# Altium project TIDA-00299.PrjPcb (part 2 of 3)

## Sheet AMIC110 ICE EVM_PHY.SchDoc
size 431 x 279 mm; Date: Not shown in title block; ApprovedBy: Not shown in title block; CheckedBy: Not shown in title block; Author: Not shown in title block; CompanyName: Not shown in title block; Engineer: Not shown in title block; Organization: Not shown in title block; Address1: Not shown in title block; Address2: Not shown in title block; Address3: Not shown in title block; Address4: Not shown in title block; DocumentNumber: 1; Revision: Use project parameter SCH_Rev; SheetNumber: 3; SheetTotal: 1; PageSetup: Record=PageOptions¦CenterHorizontal=True¦CenterVertical=True¦PrintScale=1.00¦XCorrection=1.00¦YCorrection=1.00¦PrintKind=0¦BorderSize=5000000¦LeftOffset=0¦BottomOffset=0¦Orientation=2¦PaperLength=1000¦PaperWidth=1000¦Scale=100¦PaperSource=15¦PrintQuality=600¦MediaType=1¦DitherType=10¦PaperKind=Letter¦PrintScaleMode=1
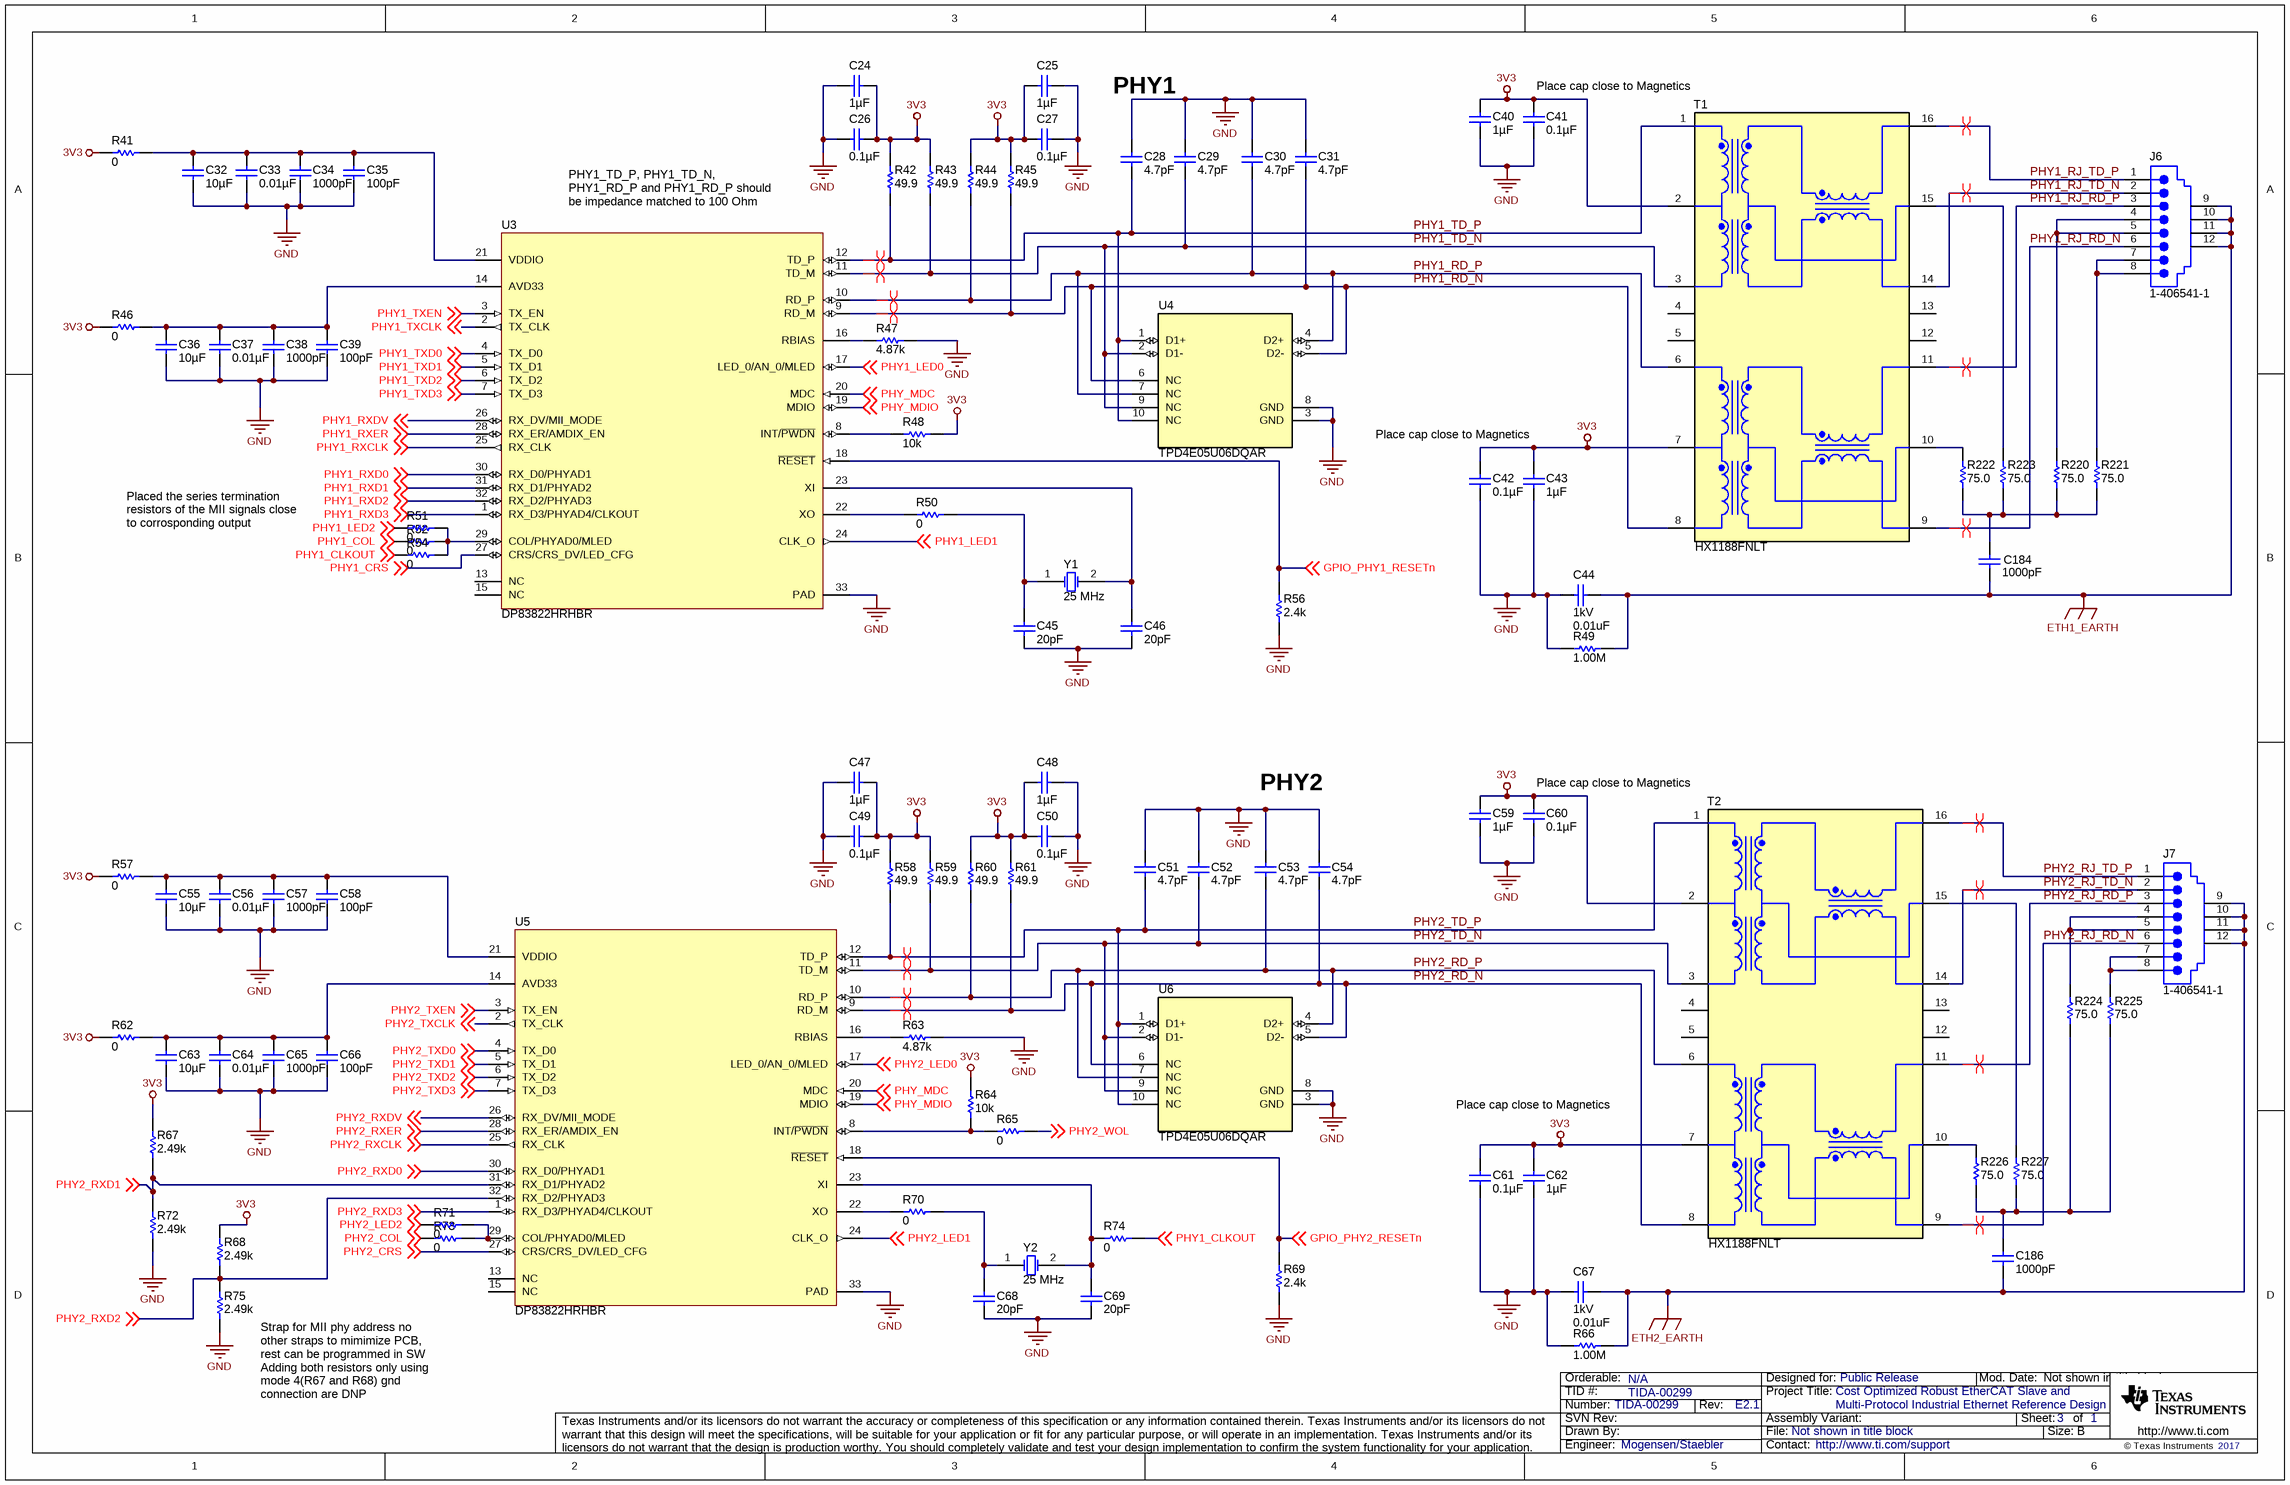
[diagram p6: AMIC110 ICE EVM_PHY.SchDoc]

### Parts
C24  ValueDisplayed: 1µF  [0402L]  (hidden comment: GRM155R70J105MA12D)
C25  ValueDisplayed: 1µF  [0402L]  (hidden comment: GRM155R70J105MA12D)
C26  ValueDisplayed: 0.1µF  [0402L]  (hidden comment: 885012205037)
C27  ValueDisplayed: 0.1µF  [0402L]  (hidden comment: 885012205037)
C28  ValueDisplayed: 4.7pF  [0201]  (hidden comment: GRM0335C1H4R7CA01D)
C29  ValueDisplayed: 4.7pF  [0201]  (hidden comment: GRM0335C1H4R7CA01D)
C30  ValueDisplayed: 4.7pF  [0201]  (hidden comment: GRM0335C1H4R7CA01D)
C31  ValueDisplayed: 4.7pF  [0201]  (hidden comment: GRM0335C1H4R7CA01D)
C32  ValueDisplayed: 10µF  [0805_HV]  (hidden comment: 885012207026)
C33  ValueDisplayed: 0.01µF  [0402]  (hidden comment: 885012205031)
C34  ValueDisplayed: 1000pF  [0402]  (hidden comment: 885012205044)
C35  ValueDisplayed: 100pF  [0402]  (hidden comment: CC0402KRX7R9BB101)
C36  ValueDisplayed: 10µF  [0805_HV]  (hidden comment: 885012207026)
C37  ValueDisplayed: 0.01µF  [0402]  (hidden comment: 885012205031)
C38  ValueDisplayed: 1000pF  [0402]  (hidden comment: 885012205044)
C39  ValueDisplayed: 100pF  [0402]  (hidden comment: CC0402KRX7R9BB101)
C40  ValueDisplayed: 1µF  [0402]  (hidden comment: GRM155R70J105MA12D)
C41  ValueDisplayed: 0.1µF  [0402]  (hidden comment: 885012205037)
C42  ValueDisplayed: 0.1µF  [0402]  (hidden comment: 885012205037)
C43  ValueDisplayed: 1µF  [0402]  (hidden comment: GRM155R70J105MA12D)
C44  VDC_V: 1kV  ValueDisplayed: 0.01uF  [1812_180]  (hidden comment: C1812C103KDRACTU)
C45  ValueDisplayed: 20pF  [0402]  (hidden comment: GRM1555C1H200JA01D)
C46  ValueDisplayed: 20pF  [0402]  (hidden comment: GRM1555C1H200JA01D)
C47  ValueDisplayed: 1µF  [0402L]  (hidden comment: GRM155R70J105MA12D)
C48  ValueDisplayed: 1µF  [0402L]  (hidden comment: GRM155R70J105MA12D)
C49  ValueDisplayed: 0.1µF  [0402L]  (hidden comment: 885012205037)
C50  ValueDisplayed: 0.1µF  [0402L]  (hidden comment: 885012205037)
C51  ValueDisplayed: 4.7pF  [0201]  (hidden comment: GRM0335C1H4R7CA01D)
C52  ValueDisplayed: 4.7pF  [0201]  (hidden comment: GRM0335C1H4R7CA01D)
C53  ValueDisplayed: 4.7pF  [0201]  (hidden comment: GRM0335C1H4R7CA01D)
C54  ValueDisplayed: 4.7pF  [0201]  (hidden comment: GRM0335C1H4R7CA01D)
C55  ValueDisplayed: 10µF  [0805_HV]  (hidden comment: 885012207026)
C56  ValueDisplayed: 0.01µF  [0402]  (hidden comment: 885012205031)
C57  ValueDisplayed: 1000pF  [0402]  (hidden comment: 885012205044)
C58  ValueDisplayed: 100pF  [0402]  (hidden comment: CC0402KRX7R9BB101)
C59  ValueDisplayed: 1µF  [0402]  (hidden comment: GRM155R70J105MA12D)
C60  ValueDisplayed: 0.1µF  [0402]  (hidden comment: 885012205037)
C61  ValueDisplayed: 0.1µF  [0402]  (hidden comment: 885012205037)
C62  ValueDisplayed: 1µF  [0402]  (hidden comment: GRM155R70J105MA12D)
C63  ValueDisplayed: 10µF  [0805_HV]  (hidden comment: 885012207026)
C64  ValueDisplayed: 0.01µF  [0402]  (hidden comment: 885012205031)
C65  ValueDisplayed: 1000pF  [0402]  (hidden comment: 885012205044)
C66  ValueDisplayed: 100pF  [0402]  (hidden comment: CC0402KRX7R9BB101)
C67  VDC_V: 1kV  ValueDisplayed: 0.01uF  [1812_180]  (hidden comment: C1812C103KDRACTU)
C68  ValueDisplayed: 20pF  [0402]  (hidden comment: GRM1555C1H200JA01D)
C69  ValueDisplayed: 20pF  [0402]  (hidden comment: GRM1555C1H200JA01D)
C184  ValueDisplayed: 1000pF  [1206_190]  (hidden comment: 202R18W102KV4E)
C186  ValueDisplayed: 1000pF  [1206_190]  (hidden comment: 202R18W102KV4E)
J6  1-406541-1  [TEC_1-406541-1]
J7  1-406541-1  [TEC_1-406541-1]
R41  ValueDisplayed: 0  [0402]  (hidden comment: CRCW04020000Z0ED)
R42  ValueDisplayed: 49.9  [0402L]  (hidden comment: CRCW040249R9FKED)
R43  ValueDisplayed: 49.9  [0402L]  (hidden comment: CRCW040249R9FKED)
R44  ValueDisplayed: 49.9  [0402L]  (hidden comment: CRCW040249R9FKED)
R45  ValueDisplayed: 49.9  [0402L]  (hidden comment: CRCW040249R9FKED)
R46  ValueDisplayed: 0  [0402]  (hidden comment: CRCW04020000Z0ED)
R47  ValueDisplayed: 4.87k  [0402]  (hidden comment: CRCW04024K87FKED)
R48  ValueDisplayed: 10k  [0402L]  (hidden comment: CRCW040210K0JNED)
R49  ValueDisplayed: 1.00M  [2010]  (hidden comment: HVC2010-1M0GT3)
R50  ValueDisplayed: 0  [0402]  (hidden comment: CRCW04020000Z0ED)
R51  ValueDisplayed: 0  [0402L]  (hidden comment: CRCW04020000Z0ED)
R52  ValueDisplayed: 0  [0402L]  (hidden comment: CRCW04020000Z0ED)
R54  ValueDisplayed: 0  [0402L]  (hidden comment: CRCW04020000Z0ED)
R56  ValueDisplayed: 2.4k  [0402]  (hidden comment: CRCW04022K40JNED)
R57  ValueDisplayed: 0  [0402]  (hidden comment: CRCW04020000Z0ED)
R58  ValueDisplayed: 49.9  [0402L]  (hidden comment: CRCW040249R9FKED)
R59  ValueDisplayed: 49.9  [0402L]  (hidden comment: CRCW040249R9FKED)
R60  ValueDisplayed: 49.9  [0402L]  (hidden comment: CRCW040249R9FKED)
R61  ValueDisplayed: 49.9  [0402L]  (hidden comment: CRCW040249R9FKED)
R62  ValueDisplayed: 0  [0402]  (hidden comment: CRCW04020000Z0ED)
R63  ValueDisplayed: 4.87k  [0402]  (hidden comment: CRCW04024K87FKED)
R64  ValueDisplayed: 10k  [0402]  (hidden comment: CRCW040210K0JNED)
R65  ValueDisplayed: 0  [0402]  (hidden comment: CRCW04020000Z0ED)
R66  ValueDisplayed: 1.00M  [2010]  (hidden comment: HVC2010-1M0GT3)
R67  ValueDisplayed: 2.49k  [0402L]  (hidden comment: CRCW04022K49FKED)
R68  ValueDisplayed: 2.49k  [0402L]  (hidden comment: CRCW04022K49FKED)
R69  ValueDisplayed: 2.4k  [0402]  (hidden comment: CRCW04022K40JNED)
R70  ValueDisplayed: 0  [0402]  (hidden comment: CRCW04020000Z0ED)
R71  ValueDisplayed: 0  [0402L]  (hidden comment: CRCW04020000Z0ED)
R72  ValueDisplayed: 2.49k  [0402L]  (hidden comment: CRCW04022K49FKED)
R73  ValueDisplayed: 0  [0402L]  (hidden comment: CRCW04020000Z0ED)
R74  ValueDisplayed: 0  [0402L]  (hidden comment: CRCW04020000Z0ED)
R75  ValueDisplayed: 2.49k  [0402L]  (hidden comment: CRCW04022K49FKED)
R220  ValueDisplayed: 75.0  [0805_HV]  (hidden comment: CRCW080575R0FKEA)
R221  ValueDisplayed: 75.0  [0805_HV]  (hidden comment: CRCW080575R0FKEA)
R222  ValueDisplayed: 75.0  [0805_HV]  (hidden comment: CRCW080575R0FKEA)
R223  ValueDisplayed: 75.0  [0805_HV]  (hidden comment: CRCW080575R0FKEA)
R224  ValueDisplayed: 75.0  [0805_HV]  (hidden comment: CRCW080575R0FKEA)
R225  ValueDisplayed: 75.0  [0805_HV]  (hidden comment: CRCW080575R0FKEA)
R226  ValueDisplayed: 75.0  [0805_HV]  (hidden comment: CRCW080575R0FKEA)
R227  ValueDisplayed: 75.0  [0805_HV]  (hidden comment: CRCW080575R0FKEA)
T1  HX1188FNLT  [Pulse_HX1188FNLT]
T2  HX1188FNLT  [Pulse_HX1188FNLT]
U3  DP83822HRHBR  [RHB0032B]
U4  TPD4E05U06DQAR  [DQA0010A]
U5  DP83822HRHBR  [RHB0032B]
U6  TPD4E05U06DQAR  [DQA0010A]
Y1  Frequency: 25 MHz  [XTAL_ABM3]  (hidden comment: CTX1175TR-ND)
Y2  Frequency: 25 MHz  [XTAL_ABM3]  (hidden comment: CTX1175TR-ND)

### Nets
3V3: C24.2 C25.1 C26.2 C27.1 C40.1 C41.1 C42.1 C43.1 C47.2 C48.1 C49.2 C50.1 C59.1 C60.1 C61.1 C62.1 R41.2 R42.2 R43.2 R44.2 R45.2 R46.2 R48.1 R57.2 R58.2 R59.2 R60.2 R61.2 R62.2 R64.2 R67.2 R68.2 T1.2(TCT) T1.7(RCT) T2.2(TCT) T2.7(RCT)
ETH1_EARTH: C44.1 C184.2 J6.9 J6.10 J6.11 J6.12 R49.2
ETH2_EARTH: C67.1 C186.2 J7.9 J7.10 J7.11 J7.12 R66.2
GND: C24.1 C25.2 C26.1 C27.2 C28.1 C29.1 C30.1 C31.1 C32.2 C33.2 C34.2 C35.2 C36.2 C37.2 C38.2 C39.2 C40.2 C41.2 C42.2 C43.2 C44.2 C45.2 C46.2 C47.1 C48.2 C49.1 C50.2 C51.1 C52.1 C53.1 C54.1 C55.2 C56.2 C57.2 C58.2 C59.2 C60.2 C61.2 C62.2 C63.2 C64.2 C65.2 C66.2 C67.2 C68.2 C69.1 R47.2 R49.1 R56.1 R63.2 R66.1 R69.1 R72.1 R75.1 U3.33(PAD) U4.3(GND) U4.8(GND) U5.33(PAD) U6.3(GND) U6.8(GND)
GPIO_PHY1_RESETn: R56.2 U3.18(~{RESET}) ; off-sheet GPIO_PHY1_RESETn
GPIO_PHY2_RESETn: R69.2 U5.18(~{RESET}) ; off-sheet GPIO_PHY2_RESETn
PHY1_CLKOUT: R54.1 R74.2 ; off-sheet PHY1_CLKOUT
PHY1_COL: R52.1 ; off-sheet PHY1_COL
PHY1_CRS: U3.27(CRS/CRS_DV/LED_CFG) ; off-sheet PHY1_CRS
PHY1_LED0: U3.17(LED_0/AN_0/MLED) ; off-sheet PHY1_LED0
PHY1_LED1: U3.24(CLK_O) ; off-sheet PHY1_LED1
PHY1_LED2: R51.1 ; off-sheet PHY1_LED2
PHY1_RD_N: C31.2 R45.1 T1.8(RD-) U3.9(RD_M) U4.5(D2-) U4.6(NC)
PHY1_RD_P: C30.2 R44.1 T1.6(RD+) U3.10(RD_P) U4.4(D2+) U4.7(NC)
PHY1_RJ_RD_N: J6.6 T1.9(RX-)
PHY1_RJ_RD_P: J6.3 T1.11(RX+)
PHY1_RJ_TD_N: J6.2 T1.14(TX-)
PHY1_RJ_TD_P: J6.1 T1.16(TX+)
PHY1_RXCLK: U3.25(RX_CLK) ; off-sheet PHY1_RXCLK
PHY1_RXD0: U3.30(RX_D0/PHYAD1) ; off-sheet PHY1_RXD0
PHY1_RXD1: U3.31(RX_D1/PHYAD2) ; off-sheet PHY1_RXD1
PHY1_RXD2: U3.32(RX_D2/PHYAD3) ; off-sheet PHY1_RXD2
PHY1_RXD3: U3.1(RX_D3/PHYAD4/CLKOUT) ; off-sheet PHY1_RXD3
PHY1_RXDV: U3.26(RX_DV/MII_MODE) ; off-sheet PHY1_RXDV
PHY1_RXER: U3.28(RX_ER/AMDIX_EN) ; off-sheet PHY1_RXER
PHY1_TD_N: C29.2 R43.1 T1.3(TD-) U3.11(TD_M) U4.2(D1-) U4.9(NC)
PHY1_TD_P: C28.2 R42.1 T1.1(TD+) U3.12(TD_P) U4.1(D1+) U4.10(NC)
PHY1_TXCLK: U3.2(TX_CLK) ; off-sheet PHY1_TXCLK
PHY1_TXD0: U3.4(TX_D0) ; off-sheet PHY1_TXD0
PHY1_TXD1: U3.5(TX_D1) ; off-sheet PHY1_TXD1
PHY1_TXD2: U3.6(TX_D2) ; off-sheet PHY1_TXD2
PHY1_TXD3: U3.7(TX_D3) ; off-sheet PHY1_TXD3
PHY1_TXEN: U3.3(TX_EN) ; off-sheet PHY1_TXEN
PHY2_COL: R73.1 ; off-sheet PHY2_COL
PHY2_CRS: U5.27(CRS/CRS_DV/LED_CFG) ; off-sheet PHY2_CRS
PHY2_LED0: U5.17(LED_0/AN_0/MLED) ; off-sheet PHY2_LED0
PHY2_LED1: U5.24(CLK_O) ; off-sheet PHY2_LED1
PHY2_LED2: R71.1 ; off-sheet PHY2_LED2
PHY2_RD_N: C54.2 R61.1 T2.8(RD-) U5.9(RD_M) U6.5(D2-) U6.6(NC)
PHY2_RD_P: C53.2 R60.1 T2.6(RD+) U5.10(RD_P) U6.4(D2+) U6.7(NC)
PHY2_RJ_RD_N: J7.6 T2.9(RX-)
PHY2_RJ_RD_P: J7.3 T2.11(RX+)
PHY2_RJ_TD_N: J7.2 T2.14(TX-)
PHY2_RJ_TD_P: J7.1 T2.16(TX+)
PHY2_RXCLK: U5.25(RX_CLK) ; off-sheet PHY2_RXCLK
PHY2_RXD0: U5.30(RX_D0/PHYAD1) ; off-sheet PHY2_RXD0
PHY2_RXD1: R67.1 R72.2 U5.31(RX_D1/PHYAD2) ; off-sheet PHY2_RXD1
PHY2_RXD2: R68.1 R75.2 U5.32(RX_D2/PHYAD3) ; off-sheet PHY2_RXD2
PHY2_RXD3: U5.1(RX_D3/PHYAD4/CLKOUT) ; off-sheet PHY2_RXD3
PHY2_RXDV: U5.26(RX_DV/MII_MODE) ; off-sheet PHY2_RXDV
PHY2_RXER: U5.28(RX_ER/AMDIX_EN) ; off-sheet PHY2_RXER
PHY2_TD_N: C52.2 R59.1 T2.3(TD-) U5.11(TD_M) U6.2(D1-) U6.9(NC)
PHY2_TD_P: C51.2 R58.1 T2.1(TD+) U5.12(TD_P) U6.1(D1+) U6.10(NC)
PHY2_TXCLK: U5.2(TX_CLK) ; off-sheet PHY2_TXCLK
PHY2_TXD0: U5.4(TX_D0) ; off-sheet PHY2_TXD0
PHY2_TXD1: U5.5(TX_D1) ; off-sheet PHY2_TXD1
PHY2_TXD2: U5.6(TX_D2) ; off-sheet PHY2_TXD2
PHY2_TXD3: U5.7(TX_D3) ; off-sheet PHY2_TXD3
PHY2_TXEN: U5.3(TX_EN) ; off-sheet PHY2_TXEN
PHY2_WOL: R65.2 ; off-sheet PHY2_WOL
PHY_MDC: U3.20(MDC) U5.20(MDC) ; off-sheet PHY_MDC
PHY_MDIO: U3.19(MDIO) U5.19(MDIO) ; off-sheet PHY_MDIO
NetC32_1: C32.1 C33.1 C34.1 C35.1 R41.1 U3.21(VDDIO)
NetC36_1: C36.1 C37.1 C38.1 C39.1 R46.1 U3.14(AVD33)
NetC45_1: C45.1 R50.2 Y1.1(OSC1)
NetC46_1: C46.1 U3.23(XI) Y1.2(OSC2)
NetC55_1: C55.1 C56.1 C57.1 C58.1 R57.1 U5.21(VDDIO)
NetC63_1: C63.1 C64.1 C65.1 C66.1 R62.1 U5.14(AVD33)
NetC68_1: C68.1 R70.2 Y2.1(OSC1)
NetC69_2: C69.2 R74.1 U5.23(XI) Y2.2(OSC2)
NetC184_1: C184.1 R220.1 R221.1 R222.1 R223.1
NetC186_1: C186.1 R224.1 R225.1 R226.1 R227.1
NetJ6_4: J6.4 J6.5 R220.2
NetJ6_7: J6.7 J6.8 R221.2
NetJ7_4: J7.4 J7.5 R224.2
NetJ7_7: J7.7 J7.8 R225.2
NetR47_1: R47.1 U3.16(RBIAS)
NetR48_2: R48.2 U3.8(INT/~{PWDN})
NetR50_1: R50.1 U3.22(XO)
NetR51_2: R51.2 R52.2 R54.2 U3.29(COL/PHYAD0/MLED)
NetR63_1: R63.1 U5.16(RBIAS)
NetR64_1: R64.1 R65.1 U5.8(INT/~{PWDN})
NetR70_1: R70.1 U5.22(XO)
NetR71_2: R71.2 R73.2 U5.29(COL/PHYAD0/MLED)
NetR222_2: R222.2 T1.10(CMT)
NetR223_2: R223.2 T1.15(CMT)
NetR226_2: R226.2 T2.10(CMT)
NetR227_2: R227.2 T2.15(CMT)

Not connected (* = marked no-connect by the designer): T1 4(NC) 5(NC) 12(NC) 13(NC); T2 4(NC) 5(NC) 12(NC) 13(NC); U3 13(NC) 15(NC); U5 13(NC) 15(NC)

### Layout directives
differential pair: PHY1_RD_N, PHY1_RD_P, PHY1_RJ_RD_N, PHY1_RJ_RD_P, PHY1_RJ_TD_N, PHY1_RJ_TD_P, PHY1_TD_N, PHY1_TD_P, PHY2_RD_N, PHY2_RD_P, PHY2_RJ_RD_N, PHY2_RJ_RD_P, PHY2_RJ_TD_N, PHY2_RJ_TD_P, PHY2_TD_N, PHY2_TD_P

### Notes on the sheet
- PHY1
- Place cap close to Magnetics
- PHY1_TD_P, PHY1_TD_N, PHY1_RD_P and PHY1_RD_P should be impedance matched to 100 Ohm
- Placed the series termination resistors of the MII signals close to corrosponding output
- PHY2
- (near R75) Strap for MII phy address no other straps to mimimize PCB, rest can be programmed in SW
  Adding both resistors only using mode 4(R67 and R68) gnd connection are DNP

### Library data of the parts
C24 C25 C47 C48 = GRM155R70J105MA12D: CAP, CERM, 1 µF, 6.3 V, +/- 20%, X7R, 0402; Manufacturer: MuRata; Polarized: N; CompType: Capacitor; Value: 1uF; U/M: EA; Cap_F: 0.000001; Tolerance_%: 20; Value1: Unknown; VDC_V: 6.3; Value2: 6.3V; TaMin_C: -55; TaMax_C: 125; Cap_Case: 0402; AEC Category: Q200
C26 C27 C49 C50 = 885012205037: CAP, CERM, 0.1 µF, 16 V, +/- 10%, X7R, 0402; Manufacturer: Wurth Elektronik; Polarized: N; CompType: Capacitor; Value: 0.1uF; U/M: EA; Cap_F: 0.0000001; Tolerance_%: 10; Value1: Unknown; VDC_V: 16; Value2: 16V; TaMin_C: -55; TaMax_C: 125; Cap_Case: 0402; AEC Category: Q200
C28-C31 C51-C54 = GRM0335C1H4R7CA01D: CAP, CERM, 4.7 pF, 50 V, +/- 5%, C0G/NP0, 0201; Manufacturer: MuRata; Polarized: N; CompType: Capacitor; Value: 4.7pF; U/M: EA; Cap_F: 0.0000000000047; Tolerance_%: 5; Value1: Unknown; VDC_V: 50; Value2: 50V; TaMin_C: -55; TaMax_C: 125; AEC Category: Q200
C32 C36 C55 C63 = 885012207026: CAP, CERM, 10 µF, 10 V, +/- 10%, X7R, 0805; Manufacturer: Wurth Elektronik; Polarized: N; CompType: Capacitor; Value: 10uF; U/M: EA; Cap_F: 0.00001; Tolerance_%: 10; Value1: Unknown; Value2: 10V; TaMin_C: -55; TaMax_C: 125; Cap_Case: 0805; AEC Category: Q200
C33 C37 C56 C64 = 885012205031: CAP, CERM, 0.01 µF, 16 V, +/- 10%, X7R, 0402; Manufacturer: Wurth Elektronik; Polarized: N; CompType: Capacitor; Value: 0.01uF; U/M: EA; Cap_F: 0.00000001; Tolerance_%: 10; Value1: Unknown; VDC_V: 16; Value2: 16V; TaMin_C: -55; TaMax_C: 125; AEC Category: Q200
C34 C38 C57 C65 = 885012205044: CAP, CERM, 1000 pF, 25 V, +/- 10%, X7R, 0402; Manufacturer: Wurth Elektronik; Polarized: N; CompType: Capacitor; Value: 1000pF; U/M: EA; Cap_F: 0.000000001; Tolerance_%: 10; Value1: Unknown; VDC_V: 25; Value2: 25V; TaMin_C: -55; TaMax_C: 125; AEC Category: Q200
C35 C39 C58 C66 = CC0402KRX7R9BB101: CAP, CERM, 100 pF, 50 V, +/- 10%, X7R, 0402; Manufacturer: Yageo America; Polarized: N; CompType: Capacitor; Value: 100pF; U/M: EA; Cap_F: 0.0000000001; Tolerance_%: 10; Value1: Unknown; VDC_V: 50; Value2: 50V; TaMin_C: -55; TaMax_C: 125; AEC Category: Q200
C40 C43 C59 C62 = GRM155R70J105MA12D: CAP, CERM, 1 µF, 6.3 V, +/- 20%, X7R, 0402; Manufacturer: MuRata; Polarized: N; CompType: Capacitor; Value: 1uF; U/M: EA; Cap_F: 0.000001; Tolerance_%: 20; Value1: Unknown; VDC_V: 6.3; Value2: 6.3V; TaMin_C: -55; TaMax_C: 125; AEC Category: Q200
C41 C42 C60 C61 = 885012205037: CAP, CERM, 0.1 µF, 16 V, +/- 10%, X7R, 0402; Manufacturer: Wurth Elektronik; Polarized: N; CompType: Capacitor; Value: 0.1uF; U/M: EA; Cap_F: 0.0000001; Tolerance_%: 10; Value1: Unknown; VDC_V: 16; Value2: 16V; TaMin_C: -55; TaMax_C: 125; AEC Category: Q200
C44 C67 = CMP-0009320-2: CAP, CERM, 0.01 uF, 1000 V, +/- 10%, X7R, 1812; Manufacturer: Kemet; TaMin_C: -55°C; Polarized: N; SizeAreaWB_mm2: 23.1; Value1: Unknown; U/M: EA; Value: 0.01uF; TaMax_C: 125°C; SizeZ_mm: 1.8; SizeX_mm: 4.5; SizeY_mm: 3.2; Cap_Case: 1812; Value2: 1000V; SizeArea_mm2: 14.4; Cap_F: 10nF; AEC Category: Q200
C45 C46 C68 C69 = GRM1555C1H200JA01D: CAP, CERM, 20 pF, 50 V, +/- 5%, C0G/NP0, 0402; Manufacturer: MuRata; Polarized: N; CompType: Capacitor; Value: 20pF; U/M: EA; Cap_F: 0.000000000020; Tolerance_%: 5; Value1: Unknown; VDC_V: 50; Value2: 50V; TaMin_C: -55; TaMax_C: 125; AEC Category: Q200
C184 C186 = 202R18W102KV4E: CAP, CERM, 1000 pF, 2000 V, +/- 10%, X7R, 1206_190; Manufacturer: Johanson Technology; Polarized: N; CompType: Capacitor; Value: 1000pF; U/M: EA; Cap_F: 0.000000001; Tolerance_%: 10; Value1: Unknown; VDC_V: 2000; Value2: 2000V; TaMin_C: -55; TaMax_C: 125; Cap_Case: 1206; AEC Category: Q200; SizeArea_mm2: 5.12; SizeAreaWB_mm2: 10.92; SizeX_mm: 3.2; SizeY_mm: 1.6; SizeZ_mm: 1.9
J6 J7 = 1-406541-1: RJ-45, No LED, tab up, R/A, TH; Manufacturer: TE Connectivity; SymbolCreator: x0208326; CompType: Connector; ContactFinish: Gold
R41 R46 R50-R52 R54 R57 R62 R65 R70 R71 R73 R74 = CRCW04020000Z0ED: RES, 0, 5%, 0.063 W, 0402; Manufacturer: Vishay-Dale; CompType: Resistor; Value: 0; Value_Code: 0000; Tolerance_%: 5; Power_W: 0.063; Value2: 0.063W; VDC_V: 50; TempCo: 200 ppm/C; EIA_Code: E24; U/M: EA; AEC Category: Q200
R42-R45 R58-R61 = CRCW040249R9FKED: RES, 49.9, 1%, 0.063 W, 0402; Manufacturer: Vishay-Dale; CompType: Resistor; Value: 49.9; Value_Code: 49R9; Tolerance_%: 1; Power_W: 0.063; Value2: 0.063W; VDC_V: 50; TempCo: 100 ppm/C; EIA_Code: E96; U/M: EA; AEC Category: Q200
R47 R63 = CRCW04024K87FKED: RES, 4.87 k, 1%, 0.063 W, 0402; Manufacturer: Vishay-Dale; CompType: Resistor; Value: 4.87k; Res_ohm: 4870; Value_Code: 4k87; Tolerance_%: 1; Power_W: 0.063; Value2: 0.063W; VDC_V: 50; TempCo: 100 ppm/C; EIA_Code: E96; U/M: EA; AEC Category: Q200
R48 R64 = CRCW040210K0JNED: RES, 10 k, 5%, 0.063 W, 0402; Manufacturer: Vishay-Dale; CompType: Resistor; Value: 10k; Res_ohm: 10000; Value_Code: 10k0; Tolerance_%: 5; Power_W: 0.063; Value2: 0.063W; VDC_V: 50; TempCo: 200 ppm/C; EIA_Code: E24; U/M: EA
R49 R66 = CMP-0016202-1: RES, 1.00 M, 2%, 0.5 W, 2010; Manufacturer: TT Electronics/IRC; Power_W: 500mW; TempCo: 100 ppm/C; Value_Code: 1M00; U/M: EA; Value: 1.00Meg; EIA_Code: E96; Res_ohm: 1M; SizeX_mm: 5; SizeY_mm: 2.5; SizeZ_mm: 1.66; Value2: 0.5W; SizeArea_mm2: 12.5; AEC Qualified: N; VDC_V: 2kV; AEC Category: Q200
R56 R69 = CRCW04022K40JNED: RES, 2.4 k, 5%, 0.063 W, 0402; Manufacturer: Vishay-Dale; CompType: Resistor; Value: 2.4k; Res_ohm: 2400; Value_Code: 2k40; Tolerance_%: 5; Power_W: 0.063; Value2: 0.063W; VDC_V: 50; TempCo: 200 ppm/C; EIA_Code: E24; U/M: EA; SizeArea_mm2: 0.5; SizeX_mm: 1; SizeZ_mm: 0.6; AEC Category: Q200
R67 R68 = CRCW04022K49FKED: RES, 2.49 k, 1%, 0.063 W, 0402; Manufacturer: Vishay-Dale; CompType: Resistor; Value: 2.49k; Res_ohm: 2490; Value_Code: 2k49; Tolerance_%: 1; Power_W: 0.063; Value2: 0.063W; VDC_V: 50; TempCo: 100 ppm/C; EIA_Code: E96; U/M: EA; AEC Category: Q200; SizeArea_mm2: 0.5; SizeZ_mm: 0.6
R72 R75 = CRCW04022K49FKED: RES, 2.49 k, 1%, 0.063 W, 0402; Manufacturer: Vishay-Dale; CompType: Resistor; Value: 2.49k; Res_ohm: 2490; Value_Code: 2k49; Tolerance_%: 1; Power_W: 0.063; Value2: 0.063W; VDC_V: 50; TempCo: 100 ppm/C; EIA_Code: E96; U/M: EA; AEC Category: Q200
R220-R227 = CRCW080575R0FKEA: RES, 75.0, 1%, 0.125 W, 0805; Manufacturer: Vishay-Dale; CompType: Resistor; Value: 75.0; Res_ohm: 75; Value_Code: 75R0; Tolerance_%: 1; Power_W: 0.125; Value2: 0.125W; VDC_V: 150; TempCo: 100 ppm/C; SizeArea_mm2: 2.5; SizeX_mm: 2; SizeY_mm: 1.25; SizeZ_mm: 1.45; EIA_Code: E96; U/M: EA; AEC Category: Q200
T1 T2 = HX1188FNLT: Transformer, 350 uH, SMT; Manufacturer: Pulse Engineering; SymbolCreator: Altium; ValueDisplayed: 350µH; Value: 350uH; Lp: 350
U3 U5 = DP83822RHBR: 10/100 Ethernet PHY, RHB0032B; Alternate PartNumber: DP83822RHBT; Manufacturer: Texas Instruments; SymbolCreator: Altium; CompType: IC; U/M: EA
U4 U6 = TPD4E05U06DQAR: 1, 4, 6 CHANNEL PROTECTION SOLUTION FOR SUPER-SPEED (UP TO 6 GBPS) INTERFACE, DQA0010A; Manufacturer: Texas Instruments; SymbolCreator: a0411947; CompType: IC; U/M: EA
Y1 Y2 = CTX1175TR-ND: Crystal, 25 MHz, 18 pF, SMD; Manufacturer: CTS ELECTRONIC COMPONENTS; U/M: EA; TaMin_C: -40; TaMax_C: 85; Frequency Stability: ±20ppm

## Sheet AMIC110 ICE EVM_Power.SchDoc
size 431 x 279 mm; Date: Not shown in title block; ApprovedBy: Not shown in title block; CheckedBy: Not shown in title block; Author: Not shown in title block; CompanyName: Not shown in title block; Engineer: Not shown in title block; Organization: Not shown in title block; Address1: Not shown in title block; Address2: Not shown in title block; Address3: Not shown in title block; Address4: Not shown in title block; DocumentNumber: 1; Revision: Use project parameter SCH_Rev; SheetNumber: 4; SheetTotal: 1; PageSetup: Record=PageOptions¦CenterHorizontal=True¦CenterVertical=True¦PrintScale=1.00¦XCorrection=1.00¦YCorrection=1.00¦PrintKind=0¦BorderSize=5000000¦LeftOffset=0¦BottomOffset=0¦Orientation=2¦PaperLength=1000¦PaperWidth=1000¦Scale=100¦PaperSource=15¦PrintQuality=600¦MediaType=1¦DitherType=10¦PaperKind=Letter¦PrintScaleMode=1
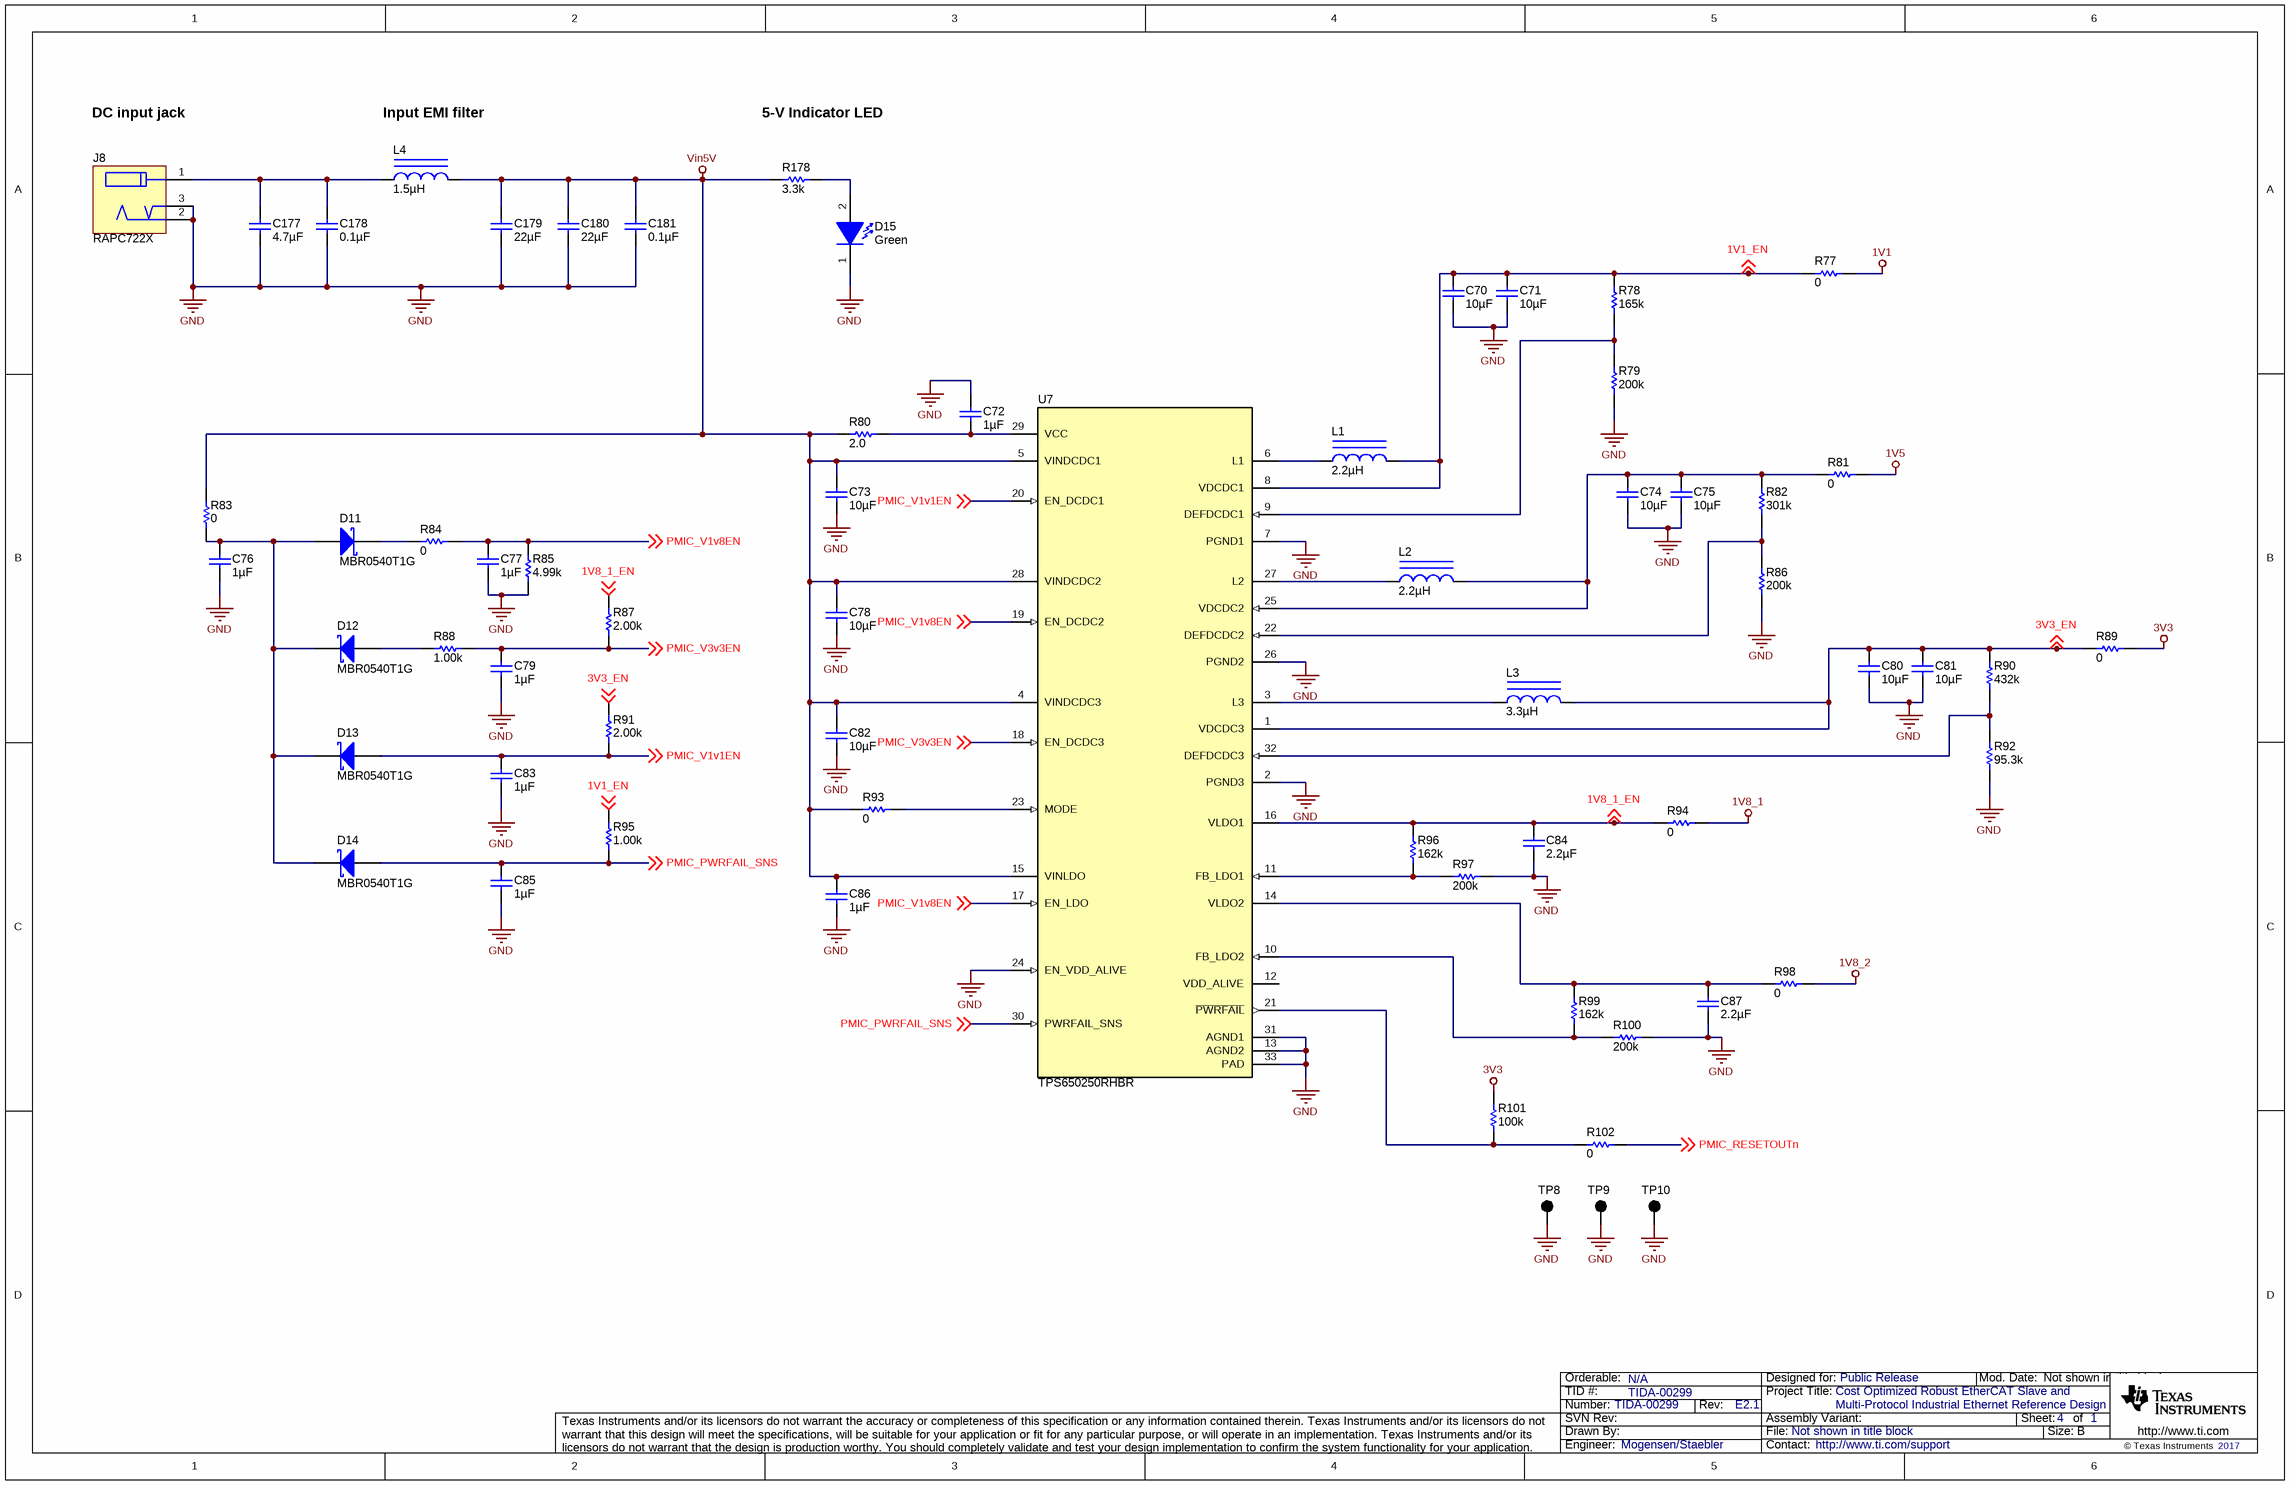
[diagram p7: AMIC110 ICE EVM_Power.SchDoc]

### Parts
C70  ValueDisplayed: 10µF  [0603]  (hidden comment: C1608X5R1E106M080AC)
C71  ValueDisplayed: 10µF  [0603]  (hidden comment: C1608X5R1E106M080AC)
C72  ValueDisplayed: 1µF  [0402]  (hidden comment: GRM155R70J105MA12D)
C73  ValueDisplayed: 10µF  [0603]  (hidden comment: C1608X5R1E106M080AC)
C74  ValueDisplayed: 10µF  [0603]  (hidden comment: C1608X5R1E106M080AC)
C75  ValueDisplayed: 10µF  [0603]  (hidden comment: C1608X5R1E106M080AC)
C76  ValueDisplayed: 1µF  [0402]  (hidden comment: GRM155R70J105MA12D)
C77  ValueDisplayed: 1µF  [0402]  (hidden comment: GRM155R70J105MA12D)
C78  ValueDisplayed: 10µF  [0603]  (hidden comment: C1608X5R1E106M080AC)
C79  ValueDisplayed: 1µF  [0402]  (hidden comment: GRM155R70J105MA12D)
C80  ValueDisplayed: 10µF  [0603]  (hidden comment: C1608X5R1E106M080AC)
C81  ValueDisplayed: 10µF  [0603]  (hidden comment: C1608X5R1E106M080AC)
C82  ValueDisplayed: 10µF  [0603]  (hidden comment: C1608X5R1E106M080AC)
C83  ValueDisplayed: 1µF  [0402]  (hidden comment: GRM155R70J105MA12D)
C84  ValueDisplayed: 2.2µF  [0603]  (hidden comment: GRM188R71A225KE15D)
C85  ValueDisplayed: 1µF  [0402]  (hidden comment: GRM155R70J105MA12D)
C86  ValueDisplayed: 1µF  [0402]  (hidden comment: GRM155R70J105MA12D)
C87  ValueDisplayed: 2.2µF  [0603]  (hidden comment: GRM188R71A225KE15D)
C177  ValueDisplayed: 4.7µF  [0603]  (hidden comment: GRM188R61C475KAAJ)
C178  ValueDisplayed: 0.1µF  [0603]  (hidden comment: GRM188R71C104KA01D)
C179  ValueDisplayed: 22µF  [0603]  (hidden comment: GRM188R61A226ME15D)
C180  ValueDisplayed: 22µF  [0603]  (hidden comment: GRM188R61A226ME15D)
C181  ValueDisplayed: 0.1µF  [0603]  (hidden comment: GRM188R71C104KA01D)
D11  MBR0540T1G  [SOD-123]
D12  MBR0540T1G  [SOD-123]
D13  MBR0540T1G  [SOD-123]
D14  MBR0540T1G  [SOD-123]
D15  value Green  [WL-SMCW_GREEN]  (hidden comment: 150060VS75000)
J8  RAPC722X  [CONN_RAPC722X]
L1  ValueDisplayed: 2.2µH  [VLCF4020]  (hidden comment: VLCF4020T-2R2N1R7)
L2  ValueDisplayed: 2.2µH  [VLCF4020]  (hidden comment: VLCF4020T-2R2N1R7)
L3  ValueDisplayed: 3.3µH  [VLCF4020]  (hidden comment: VLCF4020T-3R3N1R5)
L4  ValueDisplayed: 1.5µH  [XFL4020]  (hidden comment: XFL4020-152MEB)
R77  ValueDisplayed: 0  [0402]  (hidden comment: CRCW04020000Z0ED)
R78  ValueDisplayed: 165k  [0402]  (hidden comment: CRCW0402165KFKED)
R79  ValueDisplayed: 200k  [0402]  (hidden comment: CRCW0402200KFKED)
R80  ValueDisplayed: 2.0  [0603]  (hidden comment: CRCW06032R00JNEA)
R81  ValueDisplayed: 0  [0402]  (hidden comment: CRCW04020000Z0ED)
R82  ValueDisplayed: 301k  [0402]  (hidden comment: CRCW0402301KFKED)
R83  ValueDisplayed: 0  [0402]  (hidden comment: CRCW04020000Z0ED)
R84  ValueDisplayed: 0  [0402]  (hidden comment: CRCW04020000Z0ED)
R85  ValueDisplayed: 4.99k  [0402]  (hidden comment: CRCW04024K99FKED)
R86  ValueDisplayed: 200k  [0402]  (hidden comment: CRCW0402200KFKED)
R87  ValueDisplayed: 2.00k  [0402]  (hidden comment: CRCW04022K00FKED)
R88  ValueDisplayed: 1.00k  [0402]  (hidden comment: CRCW04021K00FKED)
R89  ValueDisplayed: 0  [0402]  (hidden comment: CRCW04020000Z0ED)
R90  ValueDisplayed: 432k  [0402]  (hidden comment: CRCW0402432KFKED)
R91  ValueDisplayed: 2.00k  [0402]  (hidden comment: CRCW04022K00FKED)
R92  ValueDisplayed: 95.3k  [0402]  (hidden comment: CRCW040295K3FKED)
R93  ValueDisplayed: 0  [0402]  (hidden comment: CRCW04020000Z0ED)
R94  ValueDisplayed: 0  [0402]  (hidden comment: CRCW04020000Z0ED)
R95  ValueDisplayed: 1.00k  [0402]  (hidden comment: CRCW04021K00FKED)
R96  ValueDisplayed: 162k  [0402]  (hidden comment: CRCW0402162KFKED)
R97  ValueDisplayed: 200k  [0402]  (hidden comment: CRCW0402200KFKED)
R98  ValueDisplayed: 0  [0402]  (hidden comment: CRCW04020000Z0ED)
R99  ValueDisplayed: 162k  [0402]  (hidden comment: CRCW0402162KFKED)
R100  ValueDisplayed: 200k  [0402]  (hidden comment: CRCW0402200KFKED)
R101  ValueDisplayed: 100k  [0402]  (hidden comment: CRCW0402100KJNED)
R102  ValueDisplayed: 0  [0402]  (hidden comment: CRCW04020000Z0ED)
R178  ValueDisplayed: 3.3k  [0402L]  (hidden comment: CRCW04023K30JNED)
TP8  5001  [Keystone5001]  (value not drawn)
TP9  5001  [Keystone5001]  (value not drawn)
TP10  5001  [Keystone5001]  (value not drawn)
U7  TPS650250RHBR  [RHB0032E]

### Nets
1V1: R77.2
1V5: R81.2
1V8_1: R94.2
1V8_2: R98.2
3V3: R89.2 R101.2
GND: C70.2 C71.2 C72.1 C73.2 C74.2 C75.2 C76.2 C77.2 C78.2 C79.2 C80.2 C81.2 C82.2 C83.2 C84.2 C85.2 C86.2 C87.2 C177.2 C178.2 C179.2 C180.2 C181.2 D15.1(K) J8.2 J8.3 R79.1 R85.1 R86.1 R92.1 R97.1 R100.1 TP8.1 TP9.1 TP10.1 U7.2(PGND3) U7.7(PGND1) U7.13(AGND2) U7.24(EN_VDD_ALIVE) U7.26(PGND2) U7.31(AGND1) U7.33(PAD)
Vin5V: C73.1 C78.1 C82.1 C86.1 C179.1 C180.1 C181.1 L4.2 R80.1 R83.2 R93.1 R178.2 U7.4(VINDCDC3) U7.5(VINDCDC1) U7.15(VINLDO) U7.28(VINDCDC2)
1V1_EN: C70.1 C71.1 L1.2 R77.1 R78.2 R95.2 U7.8(VDCDC1) ; off-sheet 1V1_EN
1V8_1_EN: C84.1 R87.2 R94.1 R96.2 U7.16(VLDO1) ; off-sheet 1V8_1_EN
3V3_EN: C80.1 C81.1 L3.2 R89.1 R90.2 R91.2 U7.1(VDCDC3) ; off-sheet 3V3_EN
PMIC_PWRFAIL_SNS: C85.1 D14.2(A) R95.1 U7.30(PWRFAIL_SNS) ; off-sheet PMIC_PWRFAIL_SNS
PMIC_RESETOUTn: R102.2 ; off-sheet PMIC_RESETOUTn
PMIC_V1v1EN: C83.1 D13.2(A) R91.1 U7.20(EN_DCDC1) ; off-sheet PMIC_V1v1EN
PMIC_V1v8EN: C77.1 R84.2 R85.2 U7.17(EN_LDO) U7.19(EN_DCDC2) ; off-sheet PMIC_V1v8EN
PMIC_V3v3EN: C79.1 R87.1 R88.2 U7.18(EN_DCDC3) ; off-sheet PMIC_V3v3EN
NetC72_2: C72.2 R80.2 U7.29(VCC)
NetC74_1: C74.1 C75.1 L2.2 R81.1 R82.2 U7.25(VDCDC2)
NetC76_1: C76.1 D11.2(A) D12.1(K) D13.1(K) D14.1(K) R83.1
NetC87_1: C87.1 R98.1 R99.2 U7.14(VLDO2)
NetC177_1: C177.1 C178.1 J8.1 L4.1
NetD11_1: D11.1(K) R84.1
NetD12_2: D12.2(A) R88.1
NetD15_2: D15.2(A) R178.1
NetL1_1: L1.1 U7.6(L1)
NetL2_1: L2.1 U7.27(L2)
NetL3_1: L3.1 U7.3(L3)
NetR78_1: R78.1 R79.2 U7.9(DEFDCDC1)
NetR82_1: R82.1 R86.2 U7.22(DEFDCDC2)
NetR90_1: R90.1 R92.2 U7.32(DEFDCDC3)
NetR93_2: R93.2 U7.23(MODE)
NetR96_1: R96.1 R97.2 U7.11(FB_LDO1)
NetR99_1: R99.1 R100.2 U7.10(FB_LDO2)
NetR101_1: R101.1 R102.1 U7.21(~{PWRFAIL})

Not connected (* = marked no-connect by the designer): U7 12(VDD_ALIVE)

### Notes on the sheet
- DC input jack
- Input EMI filter
- 5-V Indicator LED

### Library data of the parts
C70 C71 C73-C75 C78 C80-C82 = C1608X5R1E106M080AC: CAP, CERM, 10 µF, 25 V, +/- 20%, X5R, 0603; Manufacturer: TDK; Polarized: N; CompType: Capacitor; Value: 10uF; U/M: EA; Cap_F: 0.00001; Tolerance_%: 20; Value1: Unknown; VDC_V: 25; Value2: 25V; TaMin_C: -55; TaMax_C: 85
C72 C76 C77 C79 C83 C85 C86 = GRM155R70J105MA12D: as C40 on sheet AMIC110 ICE EVM_PHY
C84 C87 = GRM188R71A225KE15D: CAP, CERM, 2.2 µF, 10 V, +/- 10%, X7R, 0603; Manufacturer: MuRata; Polarized: N; CompType: Capacitor; Value: 2.2uF; U/M: EA; Cap_F: 0.0000022; Tolerance_%: 10; ESR_ohm: 0.009; Value1: 0.009 ohm; Value2: 10V; TaMin_C: -55; TaMax_C: 125
C177 = GRM188R61C475KAAJ: CAP, CERM, 4.7 µF, 16 V, +/- 10%, X5R, 0603; Manufacturer: MuRata; Polarized: N; CompType: Capacitor; Value: 4.7uF; U/M: EA; Cap_F: 0.0000047; Tolerance_%: 10; Value1: Unknown; VDC_V: 16; Value2: 16V; TaMin_C: -55; TaMax_C: 85; SizeArea_mm2: 1.28; SizeAreaWB_mm2: 4.68; SizeX_mm: 1.6; SizeY_mm: 0.8; SizeZ_mm: 1; AEC Category: Q200
C178 C181 = GRM188R71C104KA01D: CAP, CERM, 0.1 µF, 16 V, +/- 10%, X7R, 0603; Manufacturer: MuRata; Polarized: N; CompType: Capacitor; Value: 0.1uF; U/M: EA; Cap_F: 0.0000001; Tolerance_%: 10; Value1: Unknown; VDC_V: 16; Value2: 16V; TaMin_C: -55; TaMax_C: 125; SizeArea_mm2: 1.28; SizeAreaWB_mm2: 4.68; SizeX_mm: 1.6; SizeY_mm: 0.8; SizeZ_mm: 1; AEC Category: Q200
C179 C180 = GRM188R61A226ME15D: CAP, CERM, 22 µF, 10 V, +/- 20%, X5R, 0603; Manufacturer: MuRata; Polarized: N; CompType: Capacitor; Value: 22uF; U/M: EA; Cap_F: 0.000022; Tolerance_%: 20; Value1: Unknown; VDC_V: 10; Value2: 10V; TaMin_C: -55; TaMax_C: 85; SizeArea_mm2: 1.28; SizeAreaWB_mm2: 4.68; SizeX_mm: 1.6; SizeY_mm: 0.8; SizeZ_mm: 1; AEC Category: Q200
D11-D14 = MBR0540T1G: Diode, Schottky, 40 V, 0.5 A, SOD-123; Manufacturer: ON Semiconductor; U/M: EA; Vf_V: 0.51; Value: 40V; Value1: 0.5A; Value2: 0.51V; Io_A: 0.5; Vr_V: 40; TJmax_C: 150; RJC_CperW: 118; AEC Category: Q101
D15 = 150060VS75000: LED, Green, SMD; Manufacturer: Wurth Elektronik; Type: AlInGaP; Vf_V: 2; Value2: 2V; Io_A: 0.02; Value1: W; U/M: EA
J8 = RAPC722X: Power Jack, mini, 2.1mm OD, R/A, TH; Manufacturer: Switchcraft; SymbolCreator: a0799628
L1 L2 = VLCF4020T-2R2N1R7: Inductor, Shielded, Ferrite, 2.2 µH, 1.72 A, 0.059 ohm, SMD; Manufacturer: TDK; Value: 2.2uH; Ind_H: 2.2E-6; Imax_A: 1.72; Irms: 2.19A @ 40C rise; Isat: 1.72A @ 30% inductance drop; DCR_ohm: 0.059; Value2: 1.72A; AEC Category: Q200
L3 = VLCF4020T-3R3N1R5: Inductor, Shielded, Ferrite, 3.3 µH, 1.52 A, 0.078 ohm, SMD; Manufacturer: TDK; Value: 3.3uH; Ind_H: 3.3E-6; Imax_A: 1.52; Irms: 1.94A @ 40C rise; Isat: 1.52A @ 30% inductance drop; DCR_ohm: 0.078; Value2: 1.52A; AEC Category: Q200
L4 = XFL4020-152MEB: Inductor, Shielded, Composite, 1.5 µH, 4.6 A, 0.01 ohm, SMD; Manufacturer: Coilcraft; Value: 1.5uH; Ind_H: 1.5E-6; Imax_A: 4.6; Irms: 9.1A @ 40C rise; Isat: 4.6A @ 30% inductance drop; DCR_ohm: 0.01; Value2: 4.6A; AEC Category: Q200
R77 R81 R83 R84 R89 R93 R94 R98 R102 = CRCW04020000Z0ED: as R41 on sheet AMIC110 ICE EVM_PHY
R78 = CRCW0402165KFKED: RES, 165 k, 1%, 0.063 W, 0402; Manufacturer: Vishay-Dale; CompType: Resistor; Value: 165k; Res_ohm: 165000; Tolerance_%: 1; Power_W: 0.063; Value2: 0.063W; VDC_V: 50; TempCo: 100 ppm/C; EIA_Code: E96; U/M: EA; AEC Category: Q200
R79 R86 R97 R100 = CRCW0402200KFKED: RES, 200 k, 1%, 0.063 W, 0402; Manufacturer: Vishay-Dale; CompType: Resistor; Value: 200k; Res_ohm: 200000; Tolerance_%: 1; Power_W: 0.063; Value2: 0.063W; VDC_V: 50; TempCo: 100 ppm/C; EIA_Code: E96; U/M: EA; AEC Category: Q200
R80 = CRCW06032R00JNEA: RES, 2.0, 5%, 0.1 W, 0603; Manufacturer: Vishay-Dale; CompType: Resistor; Value: 2.0; Res_ohm: 2; Value_Code: 2R00; Tolerance_%: 5; Power_W: 0.1; Value2: 0.1W; VDC_V: 75; TempCo: 200 ppm/C; EIA_Code: E24; U/M: EA; AEC Category: Q200
R82 = CRCW0402301KFKED: RES, 301 k, 1%, 0.063 W, 0402; Manufacturer: Vishay-Dale; CompType: Resistor; Value: 301k; Res_ohm: 301000; Tolerance_%: 1; Power_W: 0.063; Value2: 0.063W; VDC_V: 50; TempCo: 100 ppm/C; EIA_Code: E96; U/M: EA; AEC Category: Q200
R85 = CRCW04024K99FKED: RES, 4.99 k, 1%, 0.063 W, 0402; Manufacturer: Vishay-Dale; CompType: Resistor; Value: 4.99k; Res_ohm: 4990; Value_Code: 4k99; Tolerance_%: 1; Power_W: 0.063; Value2: 0.063W; VDC_V: 50; TempCo: 100 ppm/C; EIA_Code: E96; U/M: EA; AEC Category: Q200
R87 R91 = CRCW04022K00FKED: RES, 2.00 k, 1%, 0.063 W, 0402; Manufacturer: Vishay-Dale; CompType: Resistor; Value: 2.00k; Res_ohm: 2000; Value_Code: 2k00; Tolerance_%: 1; Power_W: 0.063; Value2: 0.063W; VDC_V: 50; TempCo: 100 ppm/C; EIA_Code: E96; U/M: EA; AEC Category: Q200
R88 R95 = CRCW04021K00FKED: RES, 1.00 k, 1%, 0.063 W, 0402; Manufacturer: Vishay-Dale; CompType: Resistor; Value: 1.00k; Res_ohm: 1000; Value_Code: 1k00; Tolerance_%: 1; Power_W: 0.063; Value2: 0.063W; VDC_V: 50; TempCo: 100 ppm/C; EIA_Code: E96; U/M: EA; AEC Category: Q200
R90 = CRCW0402432KFKED: RES, 432 k, 1%, 0.063 W, 0402; Manufacturer: Vishay-Dale; CompType: Resistor; Value: 432k; Res_ohm: 432000; Tolerance_%: 1; Power_W: 0.063; Value2: 0.063W; VDC_V: 50; TempCo: 100 ppm/C; EIA_Code: E96; U/M: EA; AEC Category: Q200
R92 = CRCW040295K3FKED: RES, 95.3 k, 1%, 0.063 W, 0402; Manufacturer: Vishay-Dale; CompType: Resistor; Value: 95.3k; Res_ohm: 95300; Value_Code: 95k3; Tolerance_%: 1; Power_W: 0.063; Value2: 0.063W; VDC_V: 50; TempCo: 100 ppm/C; EIA_Code: E96; U/M: EA; AEC Category: Q200
R96 R99 = CRCW0402162KFKED: RES, 162 k, 1%, 0.063 W, 0402; Manufacturer: Vishay-Dale; CompType: Resistor; Value: 162k; Res_ohm: 162000; Tolerance_%: 1; Power_W: 0.063; Value2: 0.063W; VDC_V: 50; TempCo: 100 ppm/C; EIA_Code: E96; U/M: EA; AEC Category: Q200
R101 = CRCW0402100KJNED: RES, 100 k, 5%, 0.063 W, 0402; Manufacturer: Vishay-Dale; CompType: Resistor; Value: 100k; Res_ohm: 100000; Tolerance_%: 5; Power_W: 0.063; Value2: 0.063W; VDC_V: 50; TempCo: 200 ppm/C; EIA_Code: E24; U/M: EA; AEC Category: Q200
R178 = CRCW04023K30JNED: RES, 3.3 k, 5%, 0.063 W, 0402; Manufacturer: Vishay-Dale; CompType: Resistor; Value: 3.3k; Res_ohm: 3300; Value_Code: 3k30; Tolerance_%: 5; Power_W: 0.063; Value2: 0.063W; VDC_V: 50; TempCo: 200 ppm/C; EIA_Code: E24; U/M: EA; AEC Category: Q200; SizeArea_mm2: 0.5; SizeX_mm: 1; SizeZ_mm: 0.6
TP8-TP10 = 5001: Test Point, Miniature, Black, TH; Manufacturer: Keystone; CompType: Test Point Loop; ContactFinish: Silver
U7 = TPS650250RHBR: Power Management IC for Li-Ion Powered Systems, RHB0032E; Alternate PartNumber: TPS650250RHBT; Manufacturer: Texas Instruments; SymbolCreator: a0411947; U/M: EA

## Sheet AMIC110 ICE EVM_PS.SchDoc
size 431 x 279 mm; Date: Not shown in title block; ApprovedBy: Not shown in title block; CheckedBy: Not shown in title block; Author: Not shown in title block; CompanyName: Not shown in title block; Engineer: Not shown in title block; Organization: Not shown in title block; Address1: Not shown in title block; Address2: Not shown in title block; Address3: Not shown in title block; Address4: Not shown in title block; DocumentNumber: 1; Revision: Use project parameter SCH_Rev; SheetNumber: 6; SheetTotal: 1; PageSetup: Record=PageOptions¦CenterHorizontal=True¦CenterVertical=True¦PrintScale=1.00¦XCorrection=1.00¦YCorrection=1.00¦PrintKind=0¦BorderSize=5000000¦LeftOffset=0¦BottomOffset=0¦Orientation=2¦PaperLength=1000¦PaperWidth=1000¦Scale=100¦PaperSource=15¦PrintQuality=-3¦MediaType=1¦DitherType=10¦PrintScaleMode=1¦PaperKind=Letter¦PaperIndex=1
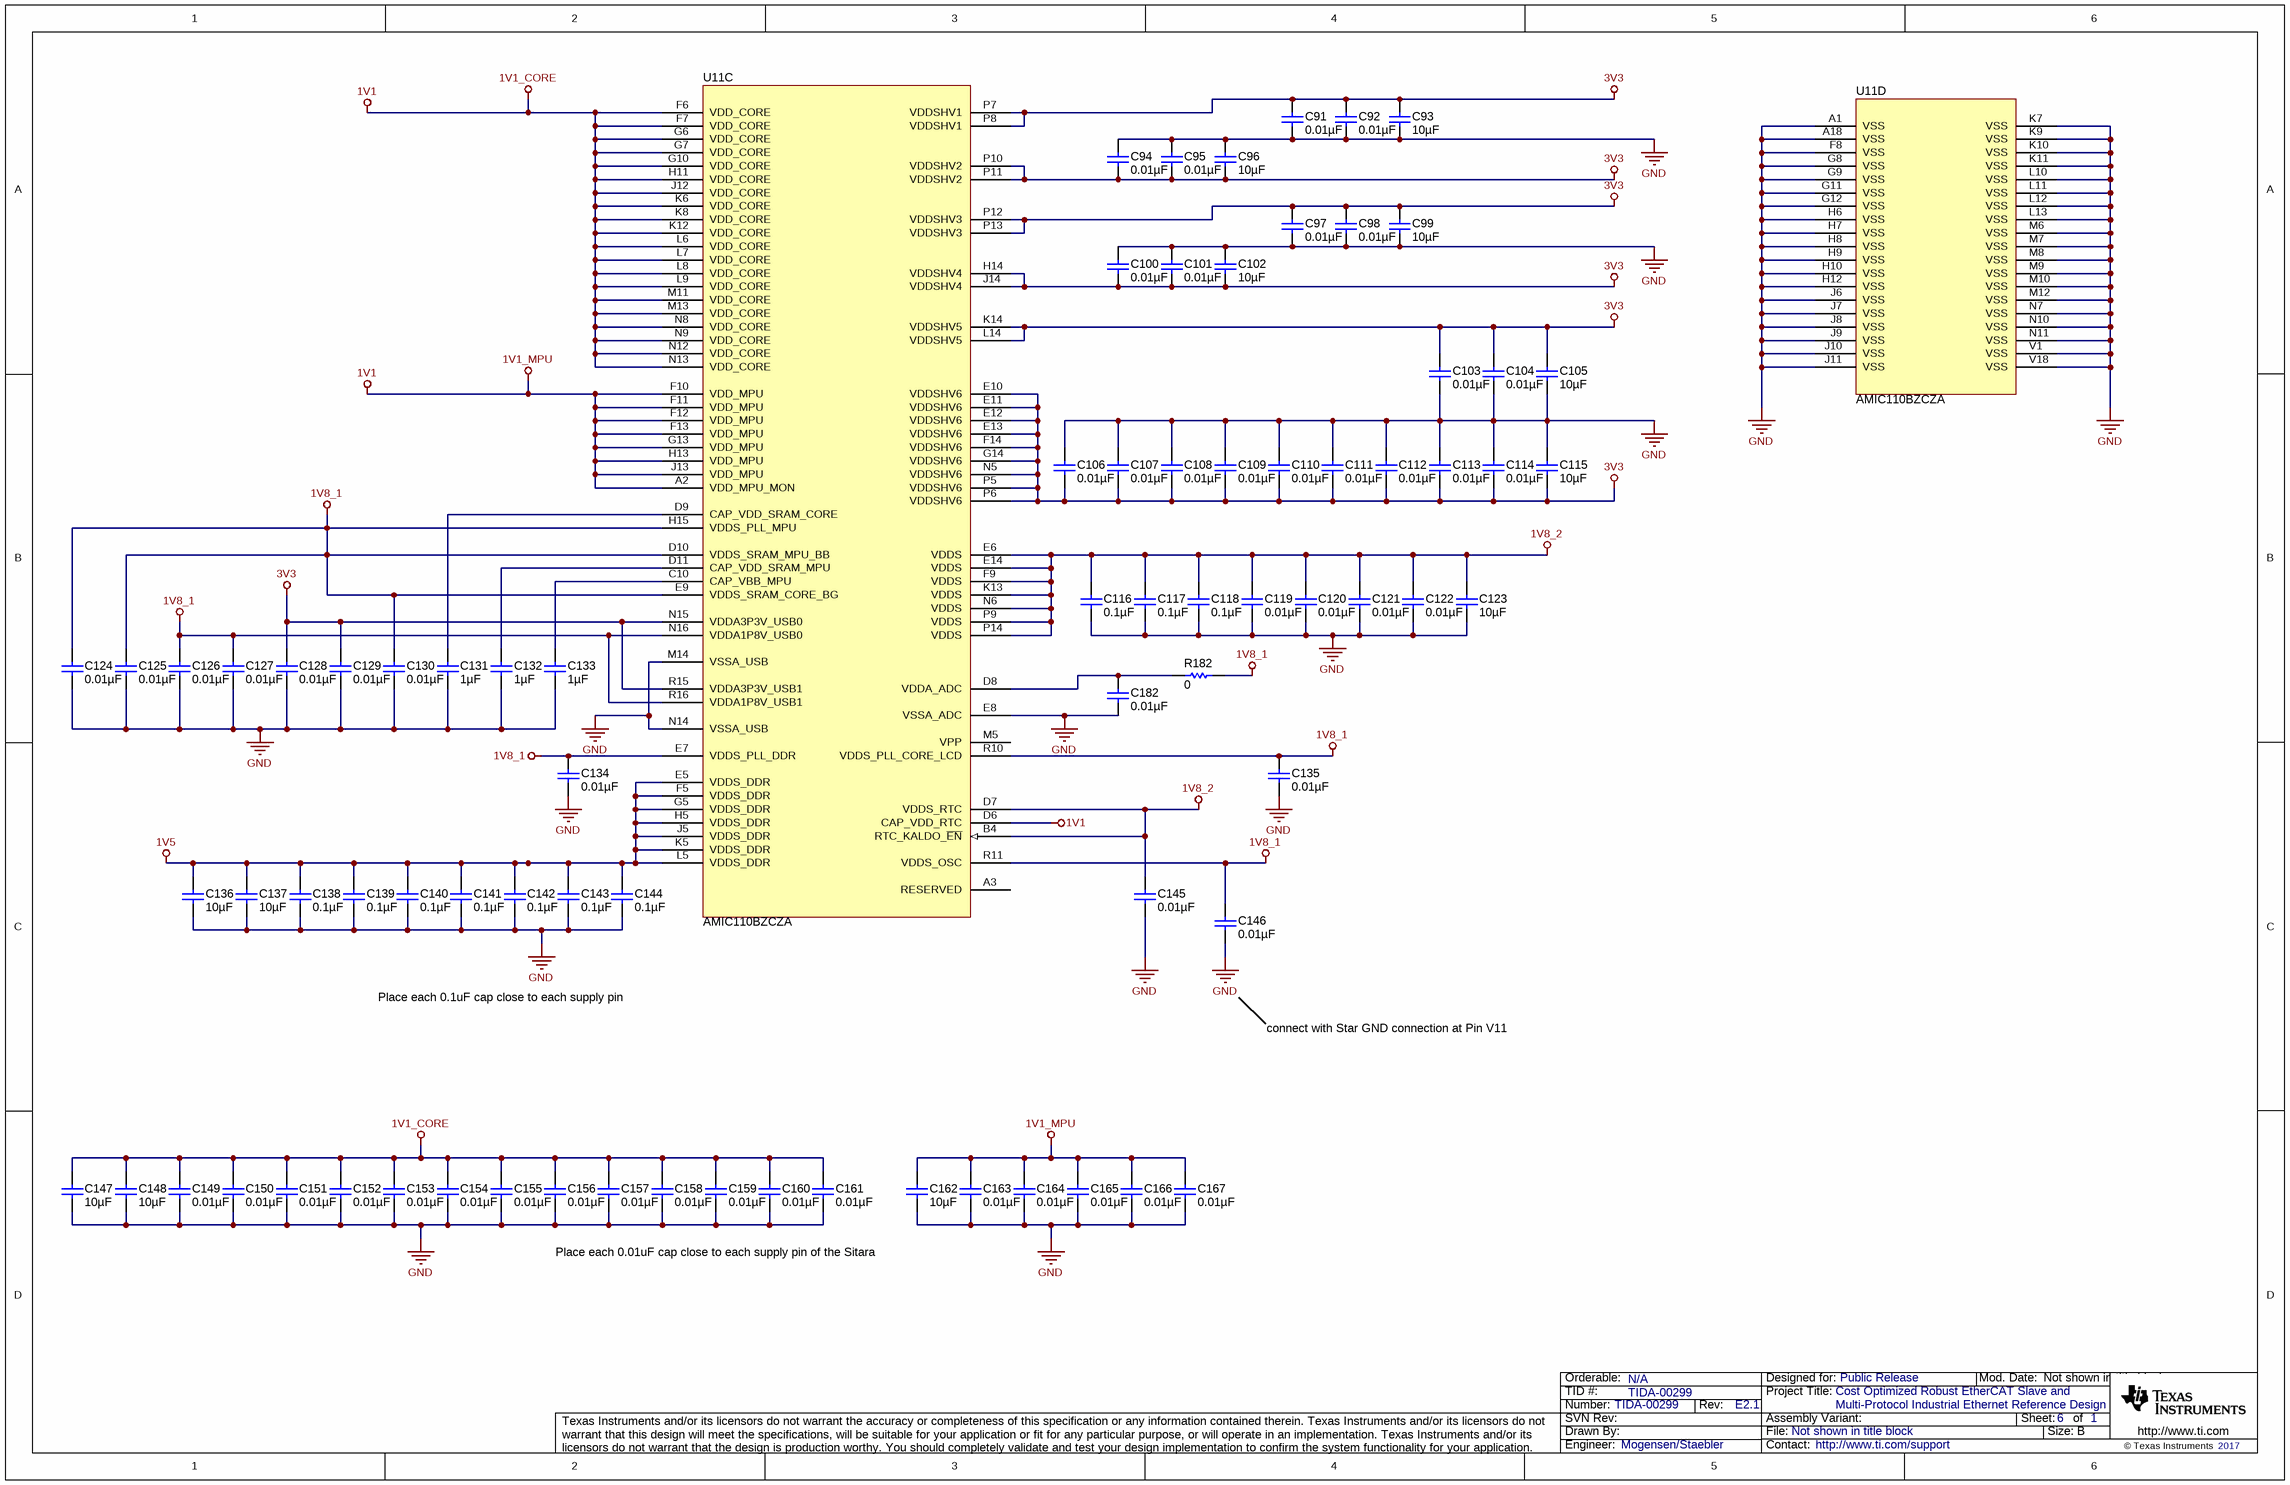
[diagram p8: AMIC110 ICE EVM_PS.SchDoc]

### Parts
C91  ValueDisplayed: 0.01µF  [0201L]  (hidden comment: GRM033R71A103KA01D)
C92  ValueDisplayed: 0.01µF  [0201L]  (hidden comment: GRM033R71A103KA01D)
C93  ValueDisplayed: 10µF  [0603L]  (hidden comment: C1608X5R1E106M080AC)
C94  ValueDisplayed: 0.01µF  [0201L]  (hidden comment: GRM033R71A103KA01D)
C95  ValueDisplayed: 0.01µF  [0201L]  (hidden comment: GRM033R71A103KA01D)
C96  ValueDisplayed: 10µF  [0603L]  (hidden comment: C1608X5R1E106M080AC)
C97  ValueDisplayed: 0.01µF  [0201L]  (hidden comment: GRM033R71A103KA01D)
C98  ValueDisplayed: 0.01µF  [0201L]  (hidden comment: GRM033R71A103KA01D)
C99  ValueDisplayed: 10µF  [0603L]  (hidden comment: C1608X5R1E106M080AC)
C100  ValueDisplayed: 0.01µF  [0201L]  (hidden comment: GRM033R71A103KA01D)
C101  ValueDisplayed: 0.01µF  [0201L]  (hidden comment: GRM033R71A103KA01D)
C102  ValueDisplayed: 10µF  [0603L]  (hidden comment: C1608X5R1E106M080AC)
C103  ValueDisplayed: 0.01µF  [0201L]  (hidden comment: GRM033R71A103KA01D)
C104  ValueDisplayed: 0.01µF  [0201L]  (hidden comment: GRM033R71A103KA01D)
C105  ValueDisplayed: 10µF  [0603L]  (hidden comment: C1608X5R1E106M080AC)
C106  ValueDisplayed: 0.01µF  [0201L]  (hidden comment: GRM033R71A103KA01D)
C107  ValueDisplayed: 0.01µF  [0201L]  (hidden comment: GRM033R71A103KA01D)
C108  ValueDisplayed: 0.01µF  [0201L]  (hidden comment: GRM033R71A103KA01D)
C109  ValueDisplayed: 0.01µF  [0201L]  (hidden comment: GRM033R71A103KA01D)
C110  ValueDisplayed: 0.01µF  [0201L]  (hidden comment: GRM033R71A103KA01D)
C111  ValueDisplayed: 0.01µF  [0201L]  (hidden comment: GRM033R71A103KA01D)
C112  ValueDisplayed: 0.01µF  [0201L]  (hidden comment: GRM033R71A103KA01D)
C113  ValueDisplayed: 0.01µF  [0201L]  (hidden comment: GRM033R71A103KA01D)
C114  ValueDisplayed: 0.01µF  [0201L]  (hidden comment: GRM033R71A103KA01D)
C115  ValueDisplayed: 10µF  [0603L]  (hidden comment: C1608X5R1E106M080AC)
C116  ValueDisplayed: 0.1µF  [0201L]  (hidden comment: CL03A104KP3NNNC)
C117  ValueDisplayed: 0.1µF  [0201L]  (hidden comment: CL03A104KP3NNNC)
C118  ValueDisplayed: 0.1µF  [0201L]  (hidden comment: CL03A104KP3NNNC)
C119  ValueDisplayed: 0.01µF  [0201L]  (hidden comment: GRM033R71A103KA01D)
C120  ValueDisplayed: 0.01µF  [0201L]  (hidden comment: GRM033R71A103KA01D)
C121  ValueDisplayed: 0.01µF  [0201L]  (hidden comment: GRM033R71A103KA01D)
C122  ValueDisplayed: 0.01µF  [0201L]  (hidden comment: GRM033R71A103KA01D)
C123  ValueDisplayed: 10µF  [0603L]  (hidden comment: C1608X5R1E106M080AC)
C124  ValueDisplayed: 0.01µF  [0201L]  (hidden comment: GRM033R71A103KA01D)
C125  ValueDisplayed: 0.01µF  [0201L]  (hidden comment: GRM033R71A103KA01D)
C126  ValueDisplayed: 0.01µF  [0201L]  (hidden comment: GRM033R71A103KA01D)
C127  ValueDisplayed: 0.01µF  [0201L]  (hidden comment: GRM033R71A103KA01D)
C128  ValueDisplayed: 0.01µF  [0201L]  (hidden comment: GRM033R71A103KA01D)
C129  ValueDisplayed: 0.01µF  [0201L]  (hidden comment: GRM033R71A103KA01D)
C130  ValueDisplayed: 0.01µF  [0201L]  (hidden comment: GRM033R71A103KA01D)
C131  ValueDisplayed: 1µF  [0402L]  (hidden comment: GRM155R70J105MA12D)
C132  ValueDisplayed: 1µF  [0402L]  (hidden comment: GRM155R70J105MA12D)
C133  ValueDisplayed: 1µF  [0402L]  (hidden comment: GRM155R70J105MA12D)
C134  ValueDisplayed: 0.01µF  [0201L]  (hidden comment: GRM033R71A103KA01D)
C135  ValueDisplayed: 0.01µF  [0201L]  (hidden comment: GRM033R71A103KA01D)
C136  ValueDisplayed: 10µF  [0603L]  (hidden comment: C1608X5R1E106M080AC)
C137  ValueDisplayed: 10µF  [0603L]  (hidden comment: C1608X5R1E106M080AC)
C138  ValueDisplayed: 0.1µF  [0201L]  (hidden comment: CL03A104KP3NNNC)
C139  ValueDisplayed: 0.1µF  [0201L]  (hidden comment: CL03A104KP3NNNC)
C140  ValueDisplayed: 0.1µF  [0201L]  (hidden comment: CL03A104KP3NNNC)
C141  ValueDisplayed: 0.1µF  [0201L]  (hidden comment: CL03A104KP3NNNC)
C142  ValueDisplayed: 0.1µF  [0201L]  (hidden comment: CL03A104KP3NNNC)
C143  ValueDisplayed: 0.1µF  [0201L]  (hidden comment: CL03A104KP3NNNC)
C144  ValueDisplayed: 0.1µF  [0201L]  (hidden comment: CL03A104KP3NNNC)
C145  ValueDisplayed: 0.01µF  [0201L]  (hidden comment: GRM033R71A103KA01D)
C146  ValueDisplayed: 0.01µF  [0201L]  (hidden comment: GRM033R71A103KA01D)
C147  ValueDisplayed: 10µF  [0603L]  (hidden comment: C1608X5R1E106M080AC)
C148  ValueDisplayed: 10µF  [0603L]  (hidden comment: C1608X5R1E106M080AC)
C149  ValueDisplayed: 0.01µF  [0201L]  (hidden comment: GRM033R71A103KA01D)
C150  ValueDisplayed: 0.01µF  [0201L]  (hidden comment: GRM033R71A103KA01D)
C151  ValueDisplayed: 0.01µF  [0201L]  (hidden comment: GRM033R71A103KA01D)
C152  ValueDisplayed: 0.01µF  [0201L]  (hidden comment: GRM033R71A103KA01D)
C153  ValueDisplayed: 0.01µF  [0201L]  (hidden comment: GRM033R71A103KA01D)
C154  ValueDisplayed: 0.01µF  [0201L]  (hidden comment: GRM033R71A103KA01D)
C155  ValueDisplayed: 0.01µF  [0201L]  (hidden comment: GRM033R71A103KA01D)
C156  ValueDisplayed: 0.01µF  [0201L]  (hidden comment: GRM033R71A103KA01D)
C157  ValueDisplayed: 0.01µF  [0201L]  (hidden comment: GRM033R71A103KA01D)
C158  ValueDisplayed: 0.01µF  [0201L]  (hidden comment: GRM033R71A103KA01D)
C159  ValueDisplayed: 0.01µF  [0201L]  (hidden comment: GRM033R71A103KA01D)
C160  ValueDisplayed: 0.01µF  [0201L]  (hidden comment: GRM033R71A103KA01D)
C161  ValueDisplayed: 0.01µF  [0201L]  (hidden comment: GRM033R71A103KA01D)
C162  ValueDisplayed: 10µF  [0603L]  (hidden comment: C1608X5R1E106M080AC)
C163  ValueDisplayed: 0.01µF  [0201L]  (hidden comment: GRM033R71A103KA01D)
C164  ValueDisplayed: 0.01µF  [0201L]  (hidden comment: GRM033R71A103KA01D)
C165  ValueDisplayed: 0.01µF  [0201L]  (hidden comment: GRM033R71A103KA01D)
C166  ValueDisplayed: 0.01µF  [0201L]  (hidden comment: GRM033R71A103KA01D)
C167  ValueDisplayed: 0.01µF  [0201L]  (hidden comment: GRM033R71A103KA01D)
C182  ValueDisplayed: 0.01µF  [0201L]  (hidden comment: GRM033R71A103KA01D)
R182  ValueDisplayed: 0  [0402L]  (hidden comment: CRCW04020000Z0ED)
U11  AMIC110BZCZA  [ZCZ0324A]  (parts C,D of 4)

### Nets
1V1: C147.1 C148.1 C149.1 C150.1 C151.1 C152.1 C153.1 C154.1 C155.1 C156.1 C157.1 C158.1 C159.1 C160.1 C161.1 C162.1 C163.1 C164.1 C165.1 C166.1 C167.1 U11.A2(VDD_MPU_MON) U11.D6(CAP_VDD_RTC) U11.F6(VDD_CORE) U11.F7(VDD_CORE) U11.F10(VDD_MPU) U11.F11(VDD_MPU) U11.F12(VDD_MPU) U11.F13(VDD_MPU) U11.G6(VDD_CORE) U11.G7(VDD_CORE) U11.G10(VDD_CORE) U11.G13(VDD_MPU) U11.H11(VDD_CORE) U11.H13(VDD_MPU) U11.J12(VDD_CORE) U11.J13(VDD_MPU) U11.K6(VDD_CORE) U11.K8(VDD_CORE) U11.K12(VDD_CORE) U11.L6(VDD_CORE) U11.L7(VDD_CORE) U11.L8(VDD_CORE) U11.L9(VDD_CORE) U11.M11(VDD_CORE) U11.M13(VDD_CORE) U11.N8(VDD_CORE) U11.N9(VDD_CORE) U11.N12(VDD_CORE) U11.N13(VDD_CORE)  [also labelled 1V1_CORE, 1V1_MPU]
1V5: C136.1 C137.1 C138.1 C139.1 C140.1 C141.1 C142.1 C143.1 C144.1 U11.E5(VDDS_DDR) U11.F5(VDDS_DDR) U11.G5(VDDS_DDR) U11.H5(VDDS_DDR) U11.J5(VDDS_DDR) U11.K5(VDDS_DDR) U11.L5(VDDS_DDR)
1V8_1: C124.1 C125.1 C126.1 C127.1 C130.1 C134.1 C135.1 C146.1 R182.1 U11.D10(VDDS_SRAM_MPU_BB) U11.E7(VDDS_PLL_DDR) U11.E9(VDDS_SRAM_CORE_BG) U11.H15(VDDS_PLL_MPU) U11.N16(VDDA1P8V_USB0) U11.R10(VDDS_PLL_CORE_LCD) U11.R11(VDDS_OSC) U11.R16(VDDA1P8V_USB1)
1V8_2: C116.1 C117.1 C118.1 C119.1 C120.1 C121.1 C122.1 C123.1 C145.1 U11.B4(RTC_KALDO_~{EN}) U11.D7(VDDS_RTC) U11.E6(VDDS) U11.E14(VDDS) U11.F9(VDDS) U11.K13(VDDS) U11.N6(VDDS) U11.P9(VDDS) U11.P14(VDDS)
3V3: C91.1 C92.1 C93.1 C94.2 C95.2 C96.2 C97.1 C98.1 C99.1 C100.2 C101.2 C102.2 C103.1 C104.1 C105.1 C106.2 C107.2 C108.2 C109.2 C110.2 C111.2 C112.2 C113.2 C114.2 C115.2 C128.1 C129.1 U11.E10(VDDSHV6) U11.E11(VDDSHV6) U11.E12(VDDSHV6) U11.E13(VDDSHV6) U11.F14(VDDSHV6) U11.G14(VDDSHV6) U11.H14(VDDSHV4) U11.J14(VDDSHV4) U11.K14(VDDSHV5) U11.L14(VDDSHV5) U11.N5(VDDSHV6) U11.N15(VDDA3P3V_USB0) U11.P5(VDDSHV6) U11.P6(VDDSHV6) U11.P7(VDDSHV1) U11.P8(VDDSHV1) U11.P10(VDDSHV2) U11.P11(VDDSHV2) U11.P12(VDDSHV3) U11.P13(VDDSHV3) U11.R15(VDDA3P3V_USB1)
GND: C91.2 C92.2 C93.2 C94.1 C95.1 C96.1 C97.2 C98.2 C99.2 C100.1 C101.1 C102.1 C103.2 C104.2 C105.2 C106.1 C107.1 C108.1 C109.1 C110.1 C111.1 C112.1 C113.1 C114.1 C115.1 C116.2 C117.2 C118.2 C119.2 C120.2 C121.2 C122.2 C123.2 C124.2 C125.2 C126.2 C127.2 C128.2 C129.2 C130.2 C131.2 C132.2 C133.2 C134.2 C135.2 C136.2 C137.2 C138.2 C139.2 C140.2 C141.2 C142.2 C143.2 C144.2 C145.2 C146.2 C147.2 C148.2 C149.2 C150.2 C151.2 C152.2 C153.2 C154.2 C155.2 C156.2 C157.2 C158.2 C159.2 C160.2 C161.2 C162.2 C163.2 C164.2 C165.2 C166.2 C167.2 C182.2 U11.A1(VSS) U11.A18(VSS) U11.E8(VSSA_ADC) U11.F8(VSS) U11.G8(VSS) U11.G9(VSS) U11.G11(VSS) U11.G12(VSS) U11.H6(VSS) U11.H7(VSS) U11.H8(VSS) U11.H9(VSS) U11.H10(VSS) U11.H12(VSS) U11.J6(VSS) U11.J7(VSS) U11.J8(VSS) U11.J9(VSS) U11.J10(VSS) U11.J11(VSS) U11.K7(VSS) U11.K9(VSS) U11.K10(VSS) U11.K11(VSS) U11.L10(VSS) U11.L11(VSS) U11.L12(VSS) U11.L13(VSS) U11.M6(VSS) U11.M7(VSS) U11.M8(VSS) U11.M9(VSS) U11.M10(VSS) U11.M12(VSS) U11.M14(VSSA_USB) U11.N7(VSS) U11.N10(VSS) U11.N11(VSS) U11.N14(VSSA_USB) U11.V1(VSS) U11.V18(VSS)
NetC131_1: C131.1 U11.D9(CAP_VDD_SRAM_CORE)
NetC132_1: C132.1 U11.D11(CAP_VDD_SRAM_MPU)
NetC133_1: C133.1 U11.C10(CAP_VBB_MPU)
NetC182_1: C182.1 R182.2 U11.D8(VDDA_ADC)

Not connected (* = marked no-connect by the designer): U11 A3(RESERVED) M5(VPP)

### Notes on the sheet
- Place each 0.1uF cap close to each supply pin
- connect with Star GND connection at Pin V11
- Place each 0.01uF cap close to each supply pin of the Sitara

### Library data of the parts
C91 C92 C94 C95 C97 C98 C100 C101 C103 C104 C106-C114 C119-C122 C124-C130 C134 C135 C145 C146 C149-C161 C163-C167 C182 = GRM033R71A103KA01D: CAP, CERM, 0.01 µF, 10 V, +/- 10%, X7R, 0201; Manufacturer: MuRata; Polarized: N; CompType: Capacitor; Value: 0.01uF; U/M: EA; Cap_F: 0.00000001; Tolerance_%: 10; Value1: Unknown; Value2: 10V; TaMin_C: -55; TaMax_C: 125; Cap_Case: 0201
C93 C96 C99 C102 C105 C115 C123 C136 C137 C147 C148 C162 = C1608X5R1E106M080AC: CAP, CERM, 10 µF, 25 V, +/- 20%, X5R, 0603; Manufacturer: TDK; Polarized: N; CompType: Capacitor; Value: 10uF; U/M: EA; Cap_F: 0.00001; Tolerance_%: 20; Value1: Unknown; VDC_V: 25; Value2: 25V; TaMin_C: -55; TaMax_C: 85; Cap_Case: 0603
C116-C118 C138-C144 = CL03A104KP3NNNC: CAP, CERM, 0.1 µF, 10 V, +/- 10%, X5R, 0201; Manufacturer: Samsung; Polarized: N; CompType: Capacitor; Value: 0.1uF; U/M: EA; Cap_F: 0.0000001; Tolerance_%: 10; Value1: Unknown; Value2: 10V; TaMin_C: -55; TaMax_C: 85; Cap_Case: 0201
C131-C133 = GRM155R70J105MA12D: as C24 on sheet AMIC110 ICE EVM_PHY
R182 = CRCW04020000Z0ED: as R41 on sheet AMIC110 ICE EVM_PHY
U11 = AMIC110BZCZA: Sitara Processors, ZCZ0324A; Alternate Manufacturer: None; Manufacturer: Texas Instruments; SymbolCreator: Altium; CompType: IC; U/M: EA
